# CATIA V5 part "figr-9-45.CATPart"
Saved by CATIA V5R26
Part number: Part1
Bounding box of the stored display mesh (mm): x -159.661 to 182.627, y -78.048 to 78.048, z 0 to 72.429
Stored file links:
  D:\_Deepak\CATIA\CATIA V5-6R2016_Deepak\Resources\Part files\Partfiles\c09_catia_v5_6r2016_prt\figr-9-45.CATPart
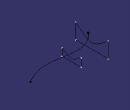
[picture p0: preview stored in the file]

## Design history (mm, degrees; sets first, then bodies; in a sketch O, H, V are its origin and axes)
Body1 (main body)
  Plane1: type Offset, RefPlane yz-plane, Offset 100
  Plane2: type Offset, RefPlane yz-plane, Offset 100, reversed
  Sketch1 on Plane1, origin (100, 0, 0), H (0, 1, 0), V (0, 0, 1)
    point P1 (0, 15.965)
    hyperbola C1
    point P2 (0, 3.0416)
    line L1 (54.8261, 44.8858) -> (54.8261, 0)
    point P5 (54.8261, 0)
    line L2 (-54.8261, 44.8858) -> (-54.8261, 0)
    point P6 (-54.8261, 0)
    line L3 (-54.8261, 0) -> (54.8261, 0)
    coincidence: P1 V, P2 V, P5 H, P6 H
    vertical: L1 V, L2 V
    horizontal: L3 H
  Sketch2 on xy-plane, origin (0, 0, 0), H (1, 0, 0), V (0, 1, 0)
    spline S1 through (-159.6608, -77.1468) (-77.8466, -31.8169) (23.6283, -41.4968) (182.6271, -11.7333)
  Sketch3 on yz-plane, origin (0, 0, 0), H (0, 1, 0), V (0, 0, 1)
    point P1 (0, 18.9787)
    hyperbola C1
    point P2 (0, 2.6681)
    line L1 (48.2237, 37.1764) -> (48.2237, 0)
    point P5 (48.2237, 0)
    line L2 (-43.6563, 34.1546) -> (-43.6563, 0)
    point P6 (-43.6563, 0)
    line L3 (-43.6563, 0) -> (48.2237, 0)
    coincidence: P1 V, P2 V, P5 H, P6 H
    vertical: L1 V, L2 V
    horizontal: L3 H
  Sketch4 on Plane2, origin (-100, 0, 0), H (0, 1, 0), V (0, 0, 1)
    point P1 (0, 140.6052)
    point P2 (0, 41.8972)
    hyperbola C1
    line L1 (78.0478, 72.4293) -> (78.0478, 0)
    point P5 (78.0478, 0)
    line L2 (-78.0478, 72.4293) -> (-78.0478, 0)
    point P6 (-78.0478, 0)
    line L3 (-78.0478, 0) -> (78.0478, 0)
    coincidence: P1 V, P2 V, P5 H, P6 H
    vertical: L1 V, L2 V
    horizontal: L3 H
  Loft1: solid, Sections (Sketch3; Sketch4), Spine Sketch2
